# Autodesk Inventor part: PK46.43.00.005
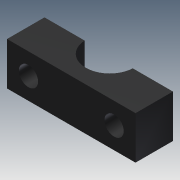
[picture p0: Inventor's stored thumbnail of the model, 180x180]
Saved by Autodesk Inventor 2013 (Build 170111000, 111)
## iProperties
Created: 2005-05
Part Number: PK46.43.00.005
Document SubType Name: Modeling
Designer: elarisa
Manufacturer: Standard
Standards Organization: Custom
Material: Silicone
Density: 1.25 g/cm^3
Author: elarisa
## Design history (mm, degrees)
sketch "Эскиз1"
  geometry: L1 (-57.8, -15.2)-(-57.8, 19.8); L2 (62.2, 19.8)-(62.2, -15.2); L3 (62.2, -15.2)-(-57.8, -15.2); L4 (-57.8, 19.8)-(-20.278, 19.8); L5 (24.678, 19.8)-(62.2, 19.8); A1 r 22.5 centre (2.2, 20.8) between (-20.278, 19.8) and (24.678, 19.8)
  constraints: 10 end point, 3 parallel, 2 perpendicular, 2 point on circle, 1 centre point, 1 vertical, 1 other
  dimensions: "d0" = 35 distance between parallel lines of L3 L4; "d1" = 1 distance from line of L4 A1.centre; "d2" = 0 distance between parallel lines of L4 L5; "d3" = 60 distance from line of A1.centre L1 (= 0.5 x d4); "d4" = 120 distance of L2.end L1.start; "d5" = 22.5 radius of A1
extrude "Выдавливание1" new body sketch "Эскиз1" distance "d6" = 40; taper "d7" = 0 deg
sketch "Эскиз2"
  geometry: L1 (0, 0)-(0, 40) reference; L2 (120, 0)-(0, 0) reference; 2 further points
  dimensions: "d8" = 20 distance from line of L2 point (20, 20); "d9" = 20 distance from line of L1 point (20, 20); "d10" = 80 distance of point (100, 20) point (20, 20); "d11" = 0 vertical distance of point (100, 20) point (20, 20)
hole "Отверстие1" sketch "Эскиз2" diameter "d12" = 18; stored, may be unused: countersink angle "d16" = 90 deg, drill point angle "d18" = 118 deg; dims "d13" = 6, "d14" = 4, "d15" = 2, "d17" = 8
body "Solid1"
